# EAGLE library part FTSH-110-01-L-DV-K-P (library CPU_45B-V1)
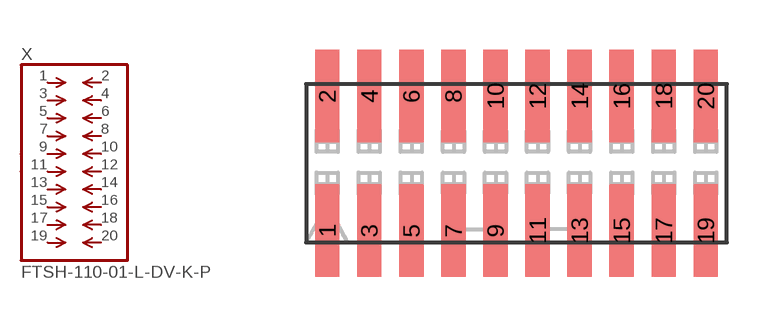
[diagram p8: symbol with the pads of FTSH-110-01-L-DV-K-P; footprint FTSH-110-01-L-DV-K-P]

Designator prefix X

## FTSH-110-01-L-DV-K-P  [FTSH-110-01-L-DV-K-P]
1  1  pas
2  2  pas
3  3  pas
4  4  pas
5  5  pas
6  6  pas
7  7  pas
8  8  pas
9  9  pas
10  10  pas
11  11  pas
12  12  pas
13  13  pas
14  14  pas
15  15  pas
16  16  pas
17  17  pas
18  18  pas
19  19  pas
20  20  pas

## Footprint FTSH-110-01-L-DV-K-P (pad centres in mm)
smd 0.737 x 2.794: 1 -5.715,-2.032; 2 -5.715,2.032; 3 -4.445,-2.032; 4 -4.445,2.032; 5 -3.175,-2.032; 6 -3.175,2.032; 7 -1.905,-2.032; 8 -1.905,2.032; 9 -0.635,-2.032; 10 -0.635,2.032; 11 0.635,-2.032; 12 0.635,2.032; 13 1.905,-2.032; 14 1.905,2.032; 15 3.175,-2.032; 16 3.175,2.032; 17 4.445,-2.032; 18 4.445,2.032; 19 5.715,-2.032; 20 5.715,2.032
